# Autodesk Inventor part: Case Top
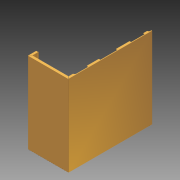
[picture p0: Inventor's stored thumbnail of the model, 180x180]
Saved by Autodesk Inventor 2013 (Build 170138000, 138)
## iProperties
Created: 2005-12
Material: Allgemein
Document SubType Name: Sheet Metal
Mass: 220.151 g
Surface Area: 4423.55 cm^2
Volume: 220.151 cm^3
Density: 1 g/cm^3
Flat Pattern Width: 37.6355 cm
Flat Pattern Length: 59.2194 cm
Flat Pattern Area: 2228.75 cm^2
Sheet Metal Rule: 1.0 mm
Sheet Metal Width: 376.355 mm
Sheet Metal Length: 592.194 mm
Sheet Metal Area: 222875.244 mm^2
Author: Autodesk, Inc.
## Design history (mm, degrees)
node "Contour Flange1"
  sketch "Sketch2"
    geometry: L1 (0, 178)-(-369, 178); L2 (-369, 178)-(-369, 0); L3 (-369, 0)-(-334, 0)
    constraints: 6 end point
    dimensions: "d2" = 35 distance of L2.end L3.end
node "Flange1"
node "Flange2"
node "Flange3"
feature "Corner1" dims "d37" = 4 (= CornerReliefSize), "d38" = 0.5 (= BendRadius), "d39" = 1 (= Thickness), "d40" = 0, "Thickness" = 1
feature "Corner2" dims "d49" = 4 (= CornerReliefSize), "d50" = 0.5 (= BendRadius), "d51" = 1 (= Thickness), "d52" = 0, "Thickness" = 1
cut "Cut3" dims "d70" = 1 (= Thickness), "d71" = 0
node "Flange4"
node "Flange5"
node "Flange6"
feature "Corner3" dims "d99" = 4 (= CornerReliefSize), "d100" = 0.5 (= BendRadius), "d101" = 1 (= Thickness), "d102" = 0, "Thickness" = 1
feature "Corner4" dims "d108" = 4 (= CornerReliefSize), "d109" = 0.5 (= BendRadius), "d110" = 1 (= Thickness), "d111" = 0, "Thickness" = 1
workplane "Work Plane2"
mirror "Mirror1"
feature "Corner Round2" dims "d116" = 2
node "Flange7"
cut "Cut6" dims "d129" = 1 (= Thickness), "d130" = 0
body "Solid1"
face "Plate1" dims "d3" = 360 (= DEPTH), "d6" = 2 (= MinimumRemnant), "d8" = 0.5 (= BendRadius), "d9" = 1, "SeamGap" = 0.01, "Thickness" = 1
bend "Bend1" dims "d4" = 1 (= BendReliefWidth), "d5" = 0.5 (= BendReliefDepth), "d6" = 2 (= MinimumRemnant), "d7" = 0.5 (= BendRadius), "d8" = 0.5 (= BendRadius), "d9" = 1, "SeamGap" = 0.01, "Thickness" = 1
sketch "Sketch3"
  geometry: L1 (0, -12)-(0, -165); L2 (0, -165)-(-10, -165); L3 (-10, -165)-(-10, -12); L4 (-10, -12)-(0, -12)
  constraints: 8 end point
face "Plate2" dims "d10" = 12, "d11" = 12, "d14" = 2 (= MinimumRemnant), "d16" = 10, "d17" = 90 deg, "d18" = 0.5 (= BendRadius), "SeamGap" = 0.01, "Thickness" = 1
bend "Bend2" dims "d12" = 1 (= BendReliefWidth), "d13" = 0.5 (= BendReliefDepth), "d14" = 2 (= MinimumRemnant), "d15" = 0.5 (= BendRadius), "d16" = 10, "d17" = 90 deg, "d18" = 0.5 (= BendRadius), "SeamGap" = 0.01, "Thickness" = 1
sketch "Sketch4"
  geometry: L1 (-12, 0)-(-34.5, 0); L2 (-34.5, 0)-(-34.5, 10); L3 (-34.5, 10)-(-12, 10); L4 (-12, 10)-(-12, 0)
  constraints: 8 end point
face "Plate3" dims "d19" = 0, "d20" = 12, "d23" = 2 (= MinimumRemnant), "d25" = 10, "d26" = 90 deg, "d27" = 0.5 (= BendRadius), "SeamGap" = 0.01, "Thickness" = 1
bend "Bend3" dims "d21" = 1 (= BendReliefWidth), "d22" = 0.5 (= BendReliefDepth), "d23" = 2 (= MinimumRemnant), "d24" = 0.5 (= BendRadius), "d25" = 10, "d26" = 90 deg, "d27" = 0.5 (= BendRadius), "SeamGap" = 0.01, "Thickness" = 1
sketch "Sketch5"
  geometry: L1 through (178.25, 0) direction (1, 0); L2 (356.5, 0)-(356.5, -10); L3 (356.5, -10)-(0, -10); L4 through (0, -5) direction (0, 1)
  constraints: 6 end point, 1 horizontal, 1 perpendicular, 1 vertical
face "Plate4" dims "d28" = 12, "d29" = 0, "d32" = 2 (= MinimumRemnant), "d34" = 10, "d35" = 90 deg, "d36" = 0.5 (= BendRadius), "SeamGap" = 0.01, "Thickness" = 1
bend "Bend4" dims "d30" = 1 (= BendReliefWidth), "d31" = 0.5 (= BendReliefDepth), "d32" = 2 (= MinimumRemnant), "d33" = 0.5 (= BendRadius), "d34" = 10, "d35" = 90 deg, "d36" = 0.5 (= BendRadius), "SeamGap" = 0.01, "Thickness" = 1
sketch "Sketch9"
  geometry: L1 (-359.293, 0)-(0, 0) reference; L2 (-370, -168.5)-(-370, 8.5) reference; L3 (0, 0)-(0, 8.5) reference; L4 (-226.104, 0)-(-151.104, 0); L5 (-151.104, 0)-(-151.104, 7); L6 (-151.104, 7)-(-226.104, 7); L7 (-226.104, 7)-(-226.104, 0); L8 (-90, 0)-(-30, 0); L9 (-30, 0)-(-30, 7); L10 (-30, 7)-(-90, 7); L11 (-90, 7)-(-90, 0); L12 (-333, 0)-(-280, 0); L13 (-280, 0)-(-280, 7); L14 (-280, 7)-(-333, 7); L15 (-333, 7)-(-333, 0); L16 (-5, 7)-(0, 7); L17 (-367.793, 8.5)-(0, 8.5) reference; L18 (-367.793, 8.5)-(-359.293, 0) reference; A1 r 7 centre (-5, 0) between (-5, 7) and (-12, 0); 1 further point
  constraints: 26 end point, 6 parallel, 6 point on line, 4 collinear, 4 horizontal, 4 perpendicular, 2 point on circle, 1 centre point, 1 horizontal alignment, 1 tangent, 1 vertical alignment, 2 other
  dimensions: "d56" = 30 distance from line of point (-340, 0) L2; "d61" = 75 distance of L5.end L6.end; "d62" = 60 distance of L9.end L10.end; "d66" = 30 distance between parallel lines of L3 L9; "d68" = 7 distance between parallel lines of L1 L14; "d69" = 60 distance from line of point (-340, 0) L13; "d114" = 12 distance from line of L3 A1.end; "d131" = 367.79289 distance of L17.start L3.end (derived); "d132" = 143.89645 distance between parallel lines of L7 L2 (computed from d131)
sketch "Sketch11"
  geometry: L1 (12, 0)-(368.5, 0); L2 (368.5, 0)-(368.5, -10); L3 (368.5, -10)-(12, -10); L4 (12, -10)-(12, 0)
  constraints: 8 end point
face "Plate5" dims "d72" = 0, "d73" = 12, "d76" = 2 (= MinimumRemnant), "d78" = 10, "d79" = 90 deg, "d80" = 0.5 (= BendRadius), "SeamGap" = 0.01, "Thickness" = 1
bend "Bend5" dims "d74" = 1 (= BendReliefWidth), "d75" = 0.5 (= BendReliefDepth), "d76" = 2 (= MinimumRemnant), "d77" = 0.5 (= BendRadius), "d78" = 10, "d79" = 90 deg, "d80" = 0.5 (= BendRadius), "SeamGap" = 0.01, "Thickness" = 1
sketch "Sketch12"
  geometry: L1 through (-11.25, 0) direction (-1, -4.44e-16); L2 (-22.5, 0)-(-22.5, 10); L3 (-22.5, 10)-(0, 10); L4 through (0, 5) direction (0, -1)
  constraints: 6 end point, 1 horizontal, 1 perpendicular, 1 vertical
face "Plate6" dims "d81" = 12, "d82" = 0, "d85" = 2 (= MinimumRemnant), "d87" = 10, "d88" = 90 deg, "d89" = 0.5 (= BendRadius), "SeamGap" = 0.01, "Thickness" = 1
bend "Bend6" dims "d83" = 1 (= BendReliefWidth), "d84" = 0.5 (= BendReliefDepth), "d85" = 2 (= MinimumRemnant), "d86" = 0.5 (= BendRadius), "d87" = 10, "d88" = 90 deg, "d89" = 0.5 (= BendRadius), "SeamGap" = 0.01, "Thickness" = 1
sketch "Sketch13"
  geometry: L1 (0, 12)-(0, 165); L2 (0, 165)-(10, 165); L3 (10, 165)-(10, 12); L4 (10, 12)-(0, 12)
  constraints: 8 end point
face "Plate7" dims "d90" = 12, "d91" = 12, "d94" = 2 (= MinimumRemnant), "d96" = 10, "d97" = 90 deg, "d98" = 0.5 (= BendRadius), "SeamGap" = 0.01, "Thickness" = 1
bend "Bend7" dims "d92" = 1 (= BendReliefWidth), "d93" = 0.5 (= BendReliefDepth), "d94" = 2 (= MinimumRemnant), "d95" = 0.5 (= BendRadius), "d96" = 10, "d97" = 90 deg, "d98" = 0.5 (= BendRadius), "SeamGap" = 0.01, "Thickness" = 1
sketch "Sketch16"
  geometry: L1 (0, 7)-(0, 346); L2 (0, 346)-(-10, 346); L3 (-10, 346)-(-10, 7); L4 (-10, 7)-(0, 7)
  constraints: 8 end point
face "Plate8" dims "d117" = 11, "d118" = 7, "d121" = 2 (= MinimumRemnant), "d123" = 10, "d124" = 0, "d125" = 0.5 (= BendRadius), "SeamGap" = 0.01, "Thickness" = 1
bend "Bend8" dims "d119" = 1 (= BendReliefWidth), "d120" = 0.5 (= BendReliefDepth), "d121" = 2 (= MinimumRemnant), "d122" = 0.5 (= BendRadius), "d123" = 10, "d124" = 0, "d125" = 0.5 (= BendRadius), "SeamGap" = 0.01, "Thickness" = 1
sketch "Sketch17"
  geometry: L1 (-84.012, -9.707)-(434.002, -9.707) reference; L2 (-10, -9.207)-(-10, 167.793) reference; C1 r 6 at (3, -49.707); C2 r 6 at (3, 30.293)
  constraints: 2 centre point, 1 equal radius, 1 symmetric about line
  dimensions: "d126" = 80 distance of C2.centre C1.centre; "d127" = 13 distance from line of C1.centre L2; "d128" = 12 diameter of C2
feature "Definition1" dims "d0" = 1 (derived)
other parameters: "BendRadius" = 0.5, "BendReliefWidth" = 1 (= Thickness), "BendReliefDepth" = 0.5 (= 0.5 x Thickness), "CornerReliefSize" = 4 (= 4 x Thickness), "MinimumRemnant" = 2 (= 2 x Thickness), "TransitionRadius" = 0.5 (= BendRadius), "d16_1" = 142 [user parameter], "JacobiRadiusSize" = 1 (derived), "GapSize" = 1 (derived), "d16_1" = 142, "BendRadius" = 0.5, "BendReliefDepth" = 0.5, "BendReliefWidth" = 1, "CornerReliefSize" = 4, "JacobiRadiusSize" = 1, "MinimumRemnant" = 2, "Thickness" = 1, "TransitionRadius" = 0.5, "GapSize" = 1
